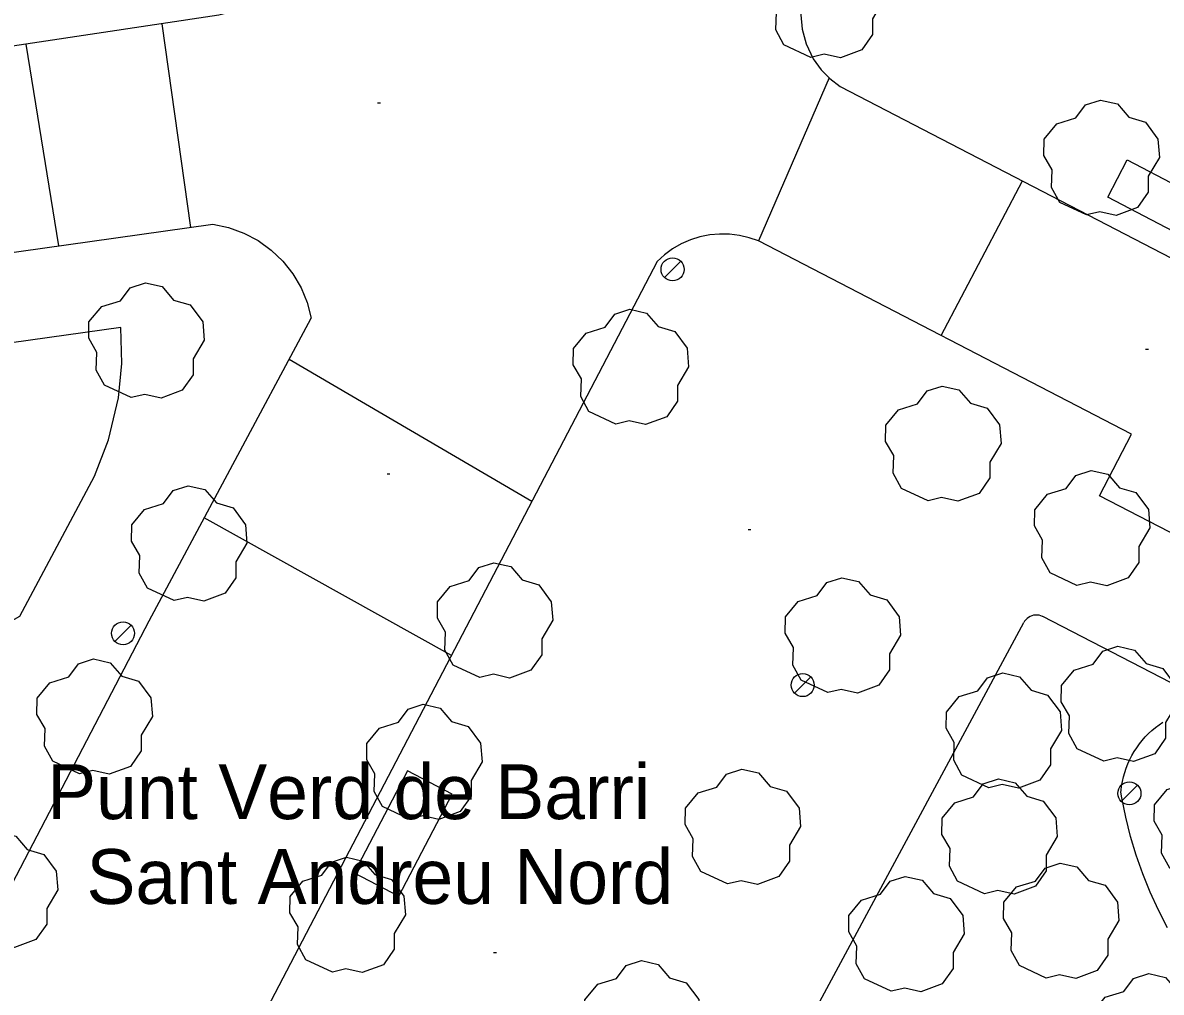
# Model space of a CAD drawing. Extents: x 431390 to 432653, y 4586754 to 4589600.
# Drawn here: x 431995.94 to 432035.41, y 4587863.28 to 4587896.91 of the extents above; entities that cross this region are included whole.
import ezdxf

# ---------------------------------------------------------------- set-up
doc = ezdxf.new("R2010")
doc.units = 0
for name, color, linetype in [('COM_17LS_LN', 7, 'Continuous'), ('COM_51_LN', 7, 'Continuous'), ('CON_09_LN', 7, 'Continuous'), ('ENE_06_PT', 7, 'Continuous'), ('ORO_03_PT', 7, 'Continuous'), ('TOP_09VI_TX', 7, 'Continuous'), ('VEG_03_PT', 7, 'Continuous'), ('VEG_07LS_LN', 7, 'Continuous')]:
    doc.layers.add(name, color=color, linetype=linetype)

msp = doc.modelspace()

# ---------------------------------------------------------------- linework, layer by layer
at = {"layer": 'COM_17LS_LN'}
for points in [[(432023.029, 4587898.053), (432022.937, 4587897.618), (432022.91, 4587897.178), (432022.958, 4587896.684), (432023.099, 4587896.169), (432023.347, 4587895.658), (432023.622, 4587895.276), (432023.922, 4587894.97), (432024.278, 4587894.699), (432082.573, 4587864.465), (432082.952, 4587864.358), (432083.334, 4587864.302), (432084.121, 4587864.341), (432084.772, 4587864.539), (432085.34, 4587864.864), (432085.77, 4587865.243), (432086.031, 4587865.564), (432086.293, 4587866.015), (432117.451, 4587929.895)], [(431969.164, 4587895.01), (431987.044, 4587897.683), (432002.579, 4587899.912), (432002.885, 4587899.835), (432003.168, 4587899.695), (432003.414, 4587899.496), (432003.61, 4587899.248), (432003.748, 4587898.964), (432003.821, 4587898.656), (432003.825, 4587898.34), (432003.761, 4587898.031), (432003.631, 4587897.743), (432003.441, 4587897.49), (432003.202, 4587897.285), (432002.739, 4587897.163), (431987.582, 4587894.892), (431968.334, 4587891.955)], [(431966.336, 4587884.604), (431982.344, 4587887.076), (432002.527, 4587889.915), (432003.074, 4587889.799), (432003.601, 4587889.609), (432004.096, 4587889.348), (432004.55, 4587889.021), (432004.955, 4587888.635), (432005.303, 4587888.196), (432005.588, 4587887.714), (432005.803, 4587887.197), (432005.944, 4587886.656)], [(432079.997, 4587856.242), (432062.182, 4587865.548), (432033.272, 4587880.499), (432034.375, 4587882.631), (432021.45, 4587889.336), (432021.123, 4587889.45), (432020.787, 4587889.528), (432020.444, 4587889.571), (432020.098, 4587889.576), (432019.754, 4587889.544), (432019.415, 4587889.475), (432019.086, 4587889.37), (432018.769, 4587889.231), (432018.47, 4587889.059), (432018.19, 4587888.855), (432017.935, 4587888.623), (432002.52, 4587859.089), (431993.611, 4587841.579)], [(431984.043, 4587845.396), (431992.548, 4587861.242), (432000.321, 4587876.164), (432005.944, 4587886.656)], [(431993.644, 4587885.535), (431993.574, 4587886.03), (431988.722, 4587885.347), (431988.652, 4587885.842), (431983.206, 4587885.076), (431981.786, 4587879.844), (431991.067, 4587873.614), (431995.837, 4587876.323), (431998.426, 4587881.173), (431998.912, 4587882.434), (431999.258, 4587883.898), (431999.372, 4587885.085), (431999.339, 4587886.336), (431993.644, 4587885.535)]]:
    msp.add_lwpolyline(points, dxfattribs=at)
at = {"layer": 'COM_51_LN'}
for points in [[(432000.758, 4587896.866), (432001.759, 4587889.807)], [(431996.044, 4587896.16), (431997.178, 4587889.163)], [(432023.892, 4587895), (432021.45, 4587889.336)], [(432027.781, 4587886.052), (432030.595, 4587891.423)], [(432013.591, 4587880.3), (432005.174, 4587885.22)], [(432010.803, 4587874.959), (432002.231, 4587879.728)]]:
    msp.add_lwpolyline(points, dxfattribs=at)
at = {"layer": 'CON_09_LN'}
for points in [[(432034.229, 4587892.145), (432037.764, 4587890.297), (432037.089, 4587889.007), (432033.554, 4587890.854), (432034.229, 4587892.145)], [(432010.831, 4587870.15), (432009.28, 4587870.96), (432007.429, 4587867.414), (432008.98, 4587866.604), (432010.831, 4587870.15)]]:
    msp.add_lwpolyline(points, dxfattribs=at)
at = {"layer": 'ENE_06_PT'}
for p, q in [((432018.75, 4587888.634), (432018.184, 4587888.068)), ((431999.699, 4587876.009), (431999.133, 4587875.443)), ((432023.261, 4587874.213), (432022.695, 4587873.647)), ((432034.588, 4587870.458), (432034.022, 4587869.892))]:
    msp.add_line(p, q, dxfattribs=at)
for centre in [(432018.467, 4587888.351), (431999.416, 4587875.726), (432022.978, 4587873.93), (432034.305, 4587870.175)]:
    msp.add_circle(centre, 0.4, dxfattribs=at)
at = {"layer": 'ORO_03_PT'}
for p, q in [((432008.238, 4587894.131), (432008.338, 4587894.131)), ((432034.868, 4587885.578), (432034.968, 4587885.578)), ((432008.569, 4587881.263), (432008.669, 4587881.263)), ((432021.084, 4587879.328), (432021.184, 4587879.328)), ((432012.262, 4587864.658), (432012.362, 4587864.658))]:
    msp.add_line(p, q, dxfattribs=at)
at = {"layer": 'VEG_03_PT'}
for points in [[(432023.257, 4587895.701), (432022.33, 4587896.136), (432022.042, 4587896.657), (432022.065, 4587897.271), (432021.783, 4587897.763), (432021.791, 4587898.326), (432022.232, 4587898.861), (432022.885, 4587899.065), (432023.22, 4587899.516), (432023.746, 4587899.686), (432024.326, 4587899.553), (432024.726, 4587899.087), (432025.3, 4587898.917), (432025.734, 4587898.334), (432025.783, 4587897.692), (432025.4, 4587897.045), (432025.4, 4587896.495), (432025.028, 4587895.961), (432024.289, 4587895.686), (432023.724, 4587895.814), (432023.257, 4587895.701)], [(432032.817, 4587890.239), (432031.89, 4587890.674), (432031.602, 4587891.195), (432031.625, 4587891.809), (432031.343, 4587892.301), (432031.351, 4587892.864), (432031.792, 4587893.399), (432032.445, 4587893.603), (432032.78, 4587894.054), (432033.306, 4587894.224), (432033.886, 4587894.091), (432034.286, 4587893.625), (432034.86, 4587893.455), (432035.294, 4587892.872), (432035.343, 4587892.23), (432034.96, 4587891.583), (432034.96, 4587891.033), (432034.588, 4587890.499), (432033.849, 4587890.224), (432033.284, 4587890.352), (432032.817, 4587890.239)], [(431999.701, 4587883.901), (431998.774, 4587884.336), (431998.486, 4587884.857), (431998.509, 4587885.471), (431998.227, 4587885.963), (431998.235, 4587886.526), (431998.676, 4587887.061), (431999.329, 4587887.265), (431999.664, 4587887.716), (432000.19, 4587887.886), (432000.77, 4587887.753), (432001.17, 4587887.287), (432001.744, 4587887.117), (432002.178, 4587886.534), (432002.227, 4587885.892), (432001.844, 4587885.245), (432001.844, 4587884.695), (432001.472, 4587884.161), (432000.733, 4587883.886), (432000.168, 4587884.014), (431999.701, 4587883.901)], [(432016.497, 4587882.981), (432015.57, 4587883.416), (432015.282, 4587883.937), (432015.305, 4587884.551), (432015.023, 4587885.043), (432015.031, 4587885.606), (432015.472, 4587886.141), (432016.125, 4587886.345), (432016.46, 4587886.796), (432016.986, 4587886.966), (432017.566, 4587886.833), (432017.966, 4587886.367), (432018.54, 4587886.197), (432018.974, 4587885.614), (432019.023, 4587884.972), (432018.64, 4587884.325), (432018.64, 4587883.775), (432018.268, 4587883.241), (432017.529, 4587882.966), (432016.964, 4587883.094), (432016.497, 4587882.981)], [(432027.327, 4587880.32), (432026.4, 4587880.755), (432026.112, 4587881.276), (432026.135, 4587881.89), (432025.853, 4587882.382), (432025.861, 4587882.945), (432026.302, 4587883.48), (432026.955, 4587883.684), (432027.29, 4587884.135), (432027.816, 4587884.305), (432028.396, 4587884.172), (432028.796, 4587883.706), (432029.37, 4587883.536), (432029.804, 4587882.953), (432029.853, 4587882.311), (432029.47, 4587881.664), (432029.47, 4587881.114), (432029.098, 4587880.58), (432028.359, 4587880.305), (432027.794, 4587880.433), (432027.327, 4587880.32)], [(432032.487, 4587877.39), (432031.56, 4587877.825), (432031.272, 4587878.346), (432031.295, 4587878.96), (432031.013, 4587879.452), (432031.021, 4587880.015), (432031.462, 4587880.55), (432032.115, 4587880.754), (432032.45, 4587881.205), (432032.976, 4587881.375), (432033.556, 4587881.242), (432033.956, 4587880.776), (432034.53, 4587880.606), (432034.964, 4587880.023), (432035.013, 4587879.381), (432034.63, 4587878.734), (432034.63, 4587878.184), (432034.258, 4587877.65), (432033.519, 4587877.375), (432032.954, 4587877.503), (432032.487, 4587877.39)], [(432001.187, 4587876.861), (432000.26, 4587877.296), (431999.972, 4587877.817), (431999.995, 4587878.431), (431999.713, 4587878.923), (431999.721, 4587879.486), (432000.162, 4587880.021), (432000.815, 4587880.225), (432001.15, 4587880.676), (432001.676, 4587880.846), (432002.256, 4587880.713), (432002.656, 4587880.247), (432003.23, 4587880.077), (432003.664, 4587879.494), (432003.713, 4587878.852), (432003.33, 4587878.205), (432003.33, 4587877.655), (432002.958, 4587877.121), (432002.219, 4587876.846), (432001.654, 4587876.974), (432001.187, 4587876.861)], [(432011.787, 4587874.191), (432010.86, 4587874.626), (432010.572, 4587875.147), (432010.595, 4587875.761), (432010.313, 4587876.253), (432010.321, 4587876.816), (432010.762, 4587877.351), (432011.415, 4587877.555), (432011.75, 4587878.006), (432012.276, 4587878.176), (432012.856, 4587878.043), (432013.256, 4587877.577), (432013.83, 4587877.407), (432014.264, 4587876.824), (432014.313, 4587876.182), (432013.93, 4587875.535), (432013.93, 4587874.985), (432013.558, 4587874.451), (432012.819, 4587874.176), (432012.254, 4587874.304), (432011.787, 4587874.191)], [(432023.847, 4587873.67), (432022.92, 4587874.105), (432022.632, 4587874.626), (432022.655, 4587875.24), (432022.373, 4587875.732), (432022.381, 4587876.295), (432022.822, 4587876.83), (432023.475, 4587877.034), (432023.81, 4587877.485), (432024.336, 4587877.655), (432024.916, 4587877.522), (432025.316, 4587877.056), (432025.89, 4587876.886), (432026.324, 4587876.303), (432026.373, 4587875.661), (432025.99, 4587875.014), (432025.99, 4587874.464), (432025.618, 4587873.93), (432024.879, 4587873.655), (432024.314, 4587873.783), (432023.847, 4587873.67)], [(432033.417, 4587871.29), (432032.49, 4587871.725), (432032.202, 4587872.246), (432032.225, 4587872.86), (432031.943, 4587873.352), (432031.951, 4587873.915), (432032.392, 4587874.45), (432033.045, 4587874.654), (432033.38, 4587875.105), (432033.906, 4587875.275), (432034.486, 4587875.142), (432034.886, 4587874.676), (432035.46, 4587874.506), (432035.894, 4587873.923), (432035.943, 4587873.281), (432035.56, 4587872.634), (432035.56, 4587872.084), (432035.188, 4587871.55), (432034.449, 4587871.275), (432033.884, 4587871.403), (432033.417, 4587871.29)], [(431997.907, 4587870.851), (431996.98, 4587871.286), (431996.692, 4587871.807), (431996.715, 4587872.421), (431996.433, 4587872.913), (431996.441, 4587873.476), (431996.882, 4587874.011), (431997.535, 4587874.215), (431997.87, 4587874.666), (431998.396, 4587874.836), (431998.976, 4587874.703), (431999.376, 4587874.237), (431999.95, 4587874.067), (432000.384, 4587873.484), (432000.433, 4587872.842), (432000.05, 4587872.195), (432000.05, 4587871.645), (431999.678, 4587871.111), (431998.939, 4587870.836), (431998.374, 4587870.964), (431997.907, 4587870.851)], [(432029.427, 4587870.37), (432028.5, 4587870.805), (432028.212, 4587871.326), (432028.235, 4587871.94), (432027.953, 4587872.432), (432027.961, 4587872.995), (432028.402, 4587873.53), (432029.055, 4587873.734), (432029.39, 4587874.185), (432029.916, 4587874.355), (432030.496, 4587874.222), (432030.896, 4587873.756), (432031.47, 4587873.586), (432031.904, 4587873.003), (432031.953, 4587872.361), (432031.57, 4587871.714), (432031.57, 4587871.164), (432031.198, 4587870.63), (432030.459, 4587870.355), (432029.894, 4587870.483), (432029.427, 4587870.37)], [(432009.337, 4587869.281), (432008.41, 4587869.716), (432008.122, 4587870.237), (432008.145, 4587870.851), (432007.863, 4587871.343), (432007.871, 4587871.906), (432008.312, 4587872.441), (432008.965, 4587872.645), (432009.3, 4587873.096), (432009.826, 4587873.266), (432010.406, 4587873.133), (432010.806, 4587872.667), (432011.38, 4587872.497), (432011.814, 4587871.914), (432011.863, 4587871.272), (432011.48, 4587870.625), (432011.48, 4587870.075), (432011.108, 4587869.541), (432010.369, 4587869.266), (432009.804, 4587869.394), (432009.337, 4587869.281)], [(432020.377, 4587867.031), (432019.45, 4587867.466), (432019.162, 4587867.987), (432019.185, 4587868.601), (432018.903, 4587869.093), (432018.911, 4587869.656), (432019.352, 4587870.191), (432020.005, 4587870.395), (432020.34, 4587870.846), (432020.866, 4587871.016), (432021.446, 4587870.883), (432021.846, 4587870.417), (432022.42, 4587870.247), (432022.854, 4587869.664), (432022.903, 4587869.022), (432022.52, 4587868.375), (432022.52, 4587867.825), (432022.148, 4587867.291), (432021.409, 4587867.016), (432020.844, 4587867.144), (432020.377, 4587867.031)], [(432036.637, 4587867.15), (432035.71, 4587867.585), (432035.422, 4587868.106), (432035.445, 4587868.72), (432035.163, 4587869.212), (432035.171, 4587869.775), (432035.612, 4587870.31), (432036.265, 4587870.514), (432036.6, 4587870.965), (432037.126, 4587871.135), (432037.706, 4587871.002), (432038.106, 4587870.536), (432038.68, 4587870.366), (432039.114, 4587869.783), (432039.163, 4587869.141), (432038.78, 4587868.494), (432038.78, 4587867.944), (432038.408, 4587867.41), (432037.669, 4587867.135), (432037.104, 4587867.263), (432036.637, 4587867.15)], [(432029.277, 4587866.69), (432028.35, 4587867.125), (432028.062, 4587867.646), (432028.085, 4587868.26), (432027.803, 4587868.752), (432027.811, 4587869.315), (432028.252, 4587869.85), (432028.905, 4587870.054), (432029.24, 4587870.505), (432029.766, 4587870.675), (432030.346, 4587870.542), (432030.746, 4587870.076), (432031.32, 4587869.906), (432031.754, 4587869.323), (432031.803, 4587868.681), (432031.42, 4587868.034), (432031.42, 4587867.484), (432031.048, 4587866.95), (432030.309, 4587866.675), (432029.744, 4587866.803), (432029.277, 4587866.69)], [(431994.627, 4587864.84), (431993.7, 4587865.275), (431993.412, 4587865.796), (431993.435, 4587866.41), (431993.153, 4587866.902), (431993.161, 4587867.465), (431993.602, 4587868), (431994.255, 4587868.204), (431994.59, 4587868.655), (431995.116, 4587868.825), (431995.696, 4587868.692), (431996.096, 4587868.226), (431996.67, 4587868.056), (431997.104, 4587867.473), (431997.153, 4587866.831), (431996.77, 4587866.184), (431996.77, 4587865.634), (431996.398, 4587865.1), (431995.659, 4587864.825), (431995.094, 4587864.953), (431994.627, 4587864.84)], [(432006.677, 4587863.971), (432005.75, 4587864.406), (432005.462, 4587864.927), (432005.485, 4587865.541), (432005.203, 4587866.033), (432005.211, 4587866.596), (432005.652, 4587867.131), (432006.305, 4587867.335), (432006.64, 4587867.786), (432007.166, 4587867.956), (432007.746, 4587867.823), (432008.146, 4587867.357), (432008.72, 4587867.187), (432009.154, 4587866.604), (432009.203, 4587865.962), (432008.82, 4587865.315), (432008.82, 4587864.765), (432008.448, 4587864.231), (432007.709, 4587863.956), (432007.144, 4587864.084), (432006.677, 4587863.971)], [(432031.417, 4587863.77), (432030.49, 4587864.205), (432030.202, 4587864.726), (432030.225, 4587865.34), (432029.943, 4587865.832), (432029.951, 4587866.395), (432030.392, 4587866.93), (432031.045, 4587867.134), (432031.38, 4587867.585), (432031.906, 4587867.755), (432032.486, 4587867.622), (432032.886, 4587867.156), (432033.46, 4587866.986), (432033.894, 4587866.403), (432033.943, 4587865.761), (432033.56, 4587865.114), (432033.56, 4587864.564), (432033.188, 4587864.03), (432032.449, 4587863.755), (432031.884, 4587863.883), (432031.417, 4587863.77)], [(432026.047, 4587863.31), (432025.12, 4587863.745), (432024.832, 4587864.266), (432024.855, 4587864.88), (432024.573, 4587865.372), (432024.581, 4587865.935), (432025.022, 4587866.47), (432025.675, 4587866.674), (432026.01, 4587867.125), (432026.536, 4587867.295), (432027.116, 4587867.162), (432027.516, 4587866.696), (432028.09, 4587866.526), (432028.524, 4587865.943), (432028.573, 4587865.301), (432028.19, 4587864.654), (432028.19, 4587864.104), (432027.818, 4587863.57), (432027.079, 4587863.295), (432026.514, 4587863.423), (432026.047, 4587863.31)], [(432016.897, 4587860.391), (432015.97, 4587860.826), (432015.682, 4587861.347), (432015.705, 4587861.961), (432015.423, 4587862.453), (432015.431, 4587863.016), (432015.872, 4587863.551), (432016.525, 4587863.755), (432016.86, 4587864.206), (432017.386, 4587864.376), (432017.966, 4587864.243), (432018.366, 4587863.777), (432018.94, 4587863.607), (432019.374, 4587863.024), (432019.423, 4587862.382), (432019.04, 4587861.735), (432019.04, 4587861.185), (432018.668, 4587860.651), (432017.929, 4587860.376), (432017.364, 4587860.504), (432016.897, 4587860.391)], [(432034.487, 4587859.94), (432033.56, 4587860.375), (432033.272, 4587860.896), (432033.295, 4587861.51), (432033.013, 4587862.002), (432033.021, 4587862.565), (432033.462, 4587863.1), (432034.115, 4587863.304), (432034.45, 4587863.755), (432034.976, 4587863.925), (432035.556, 4587863.792), (432035.956, 4587863.326), (432036.53, 4587863.156), (432036.964, 4587862.573), (432037.013, 4587861.931), (432036.63, 4587861.284), (432036.63, 4587860.734), (432036.258, 4587860.2), (432035.519, 4587859.925), (432034.954, 4587860.053), (432034.487, 4587859.94)]]:
    msp.add_lwpolyline(points, dxfattribs=at)
at = {"layer": 'VEG_07LS_LN'}
for points in [[(432037.446, 4587873.131), (432031.308, 4587876.305), (432031.291, 4587876.313), (432031.233, 4587876.336), (432031.172, 4587876.352), (432031.109, 4587876.359), (432031.046, 4587876.359), (432030.983, 4587876.351), (432030.922, 4587876.335), (432030.864, 4587876.311), (432030.809, 4587876.28), (432030.758, 4587876.243), (432030.712, 4587876.199), (432030.672, 4587876.15), (432030.639, 4587876.096)], [(432010.316, 4587837.246), (432021.625, 4587859.323), (432030.639, 4587876.096)], [(432035.63, 4587865.511), (432035.315, 4587866.121), (432035.029, 4587866.744), (432034.772, 4587867.38), (432034.544, 4587868.027), (432034.346, 4587868.683), (432034.179, 4587869.348), (432034.043, 4587870.019), (432034.009, 4587870.219), (432034.014, 4587870.275), (432034.034, 4587870.433), (432034.062, 4587870.591), (432034.098, 4587870.746), (432034.141, 4587870.9), (432034.192, 4587871.051), (432034.251, 4587871.199), (432034.317, 4587871.345), (432034.39, 4587871.487), (432034.47, 4587871.625), (432034.557, 4587871.759), (432034.65, 4587871.888), (432034.75, 4587872.012), (432034.856, 4587872.132), (432034.968, 4587872.246), (432035.085, 4587872.354), (432035.208, 4587872.456), (432035.336, 4587872.552), (432035.468, 4587872.641)]]:
    msp.add_lwpolyline(points, dxfattribs=at)

# ---------------------------------------------------------------- texts
at = {"layer": 'TOP_09VI_TX'}
for s, p in [('Punt Verd de Barri', (431996.787, 4587869.281)), ('Sant Andreu Nord', (431998.15, 4587866.34))]:
    msp.add_text(s, height=1.9, dxfattribs=at).set_placement(p)

doc.saveas('drawing.dxf')
